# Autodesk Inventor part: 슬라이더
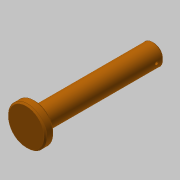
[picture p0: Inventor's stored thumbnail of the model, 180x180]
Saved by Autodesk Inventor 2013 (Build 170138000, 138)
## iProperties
Created: 2019-01
Part Number: 슬라이더
Material: 강철, 연강
Document SubType Name: Modeling
Designer: mduedu
Density: 1 g/cm^3
Author: mduedu
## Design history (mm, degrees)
sketch "스케치1"
  geometry: L1 (0, 0)-(6, 0); L2 (6, 0)-(6, 13); L3 (6, 13)-(0, 13); L4 (0, 13)-(0, 0); L5 (6, 0)-(86, 0); L6 (86, 0)-(86, 7); L7 (86, 7)-(6, 7); L8 (6, 7)-(6, 0)
  constraints: 16 end point, 4 parallel, 2 horizontal, 2 perpendicular
  dimensions: "d0" = 86 distance between parallel lines of L6 L4; "d2" = 6 distance of L2.end L3.end; "d3" = 26 diameter of L3 L1; "d4" = 14 diameter of L7 L5
revolve "회전1" sketch "스케치1" stored, may be unused: angle "d5" = 90 deg
chamfer "모따기1" distance "d6" = 1; stored, may be unused: second distance "d7" = 2, angle "d8" = 45 deg
chamfer "모따기4" distance "d24" = 1; stored, may be unused: second distance "d25" = 2, angle "d28" = 30 deg
sketch "스케치3"
  geometry: L1 (86, 6)-(86, -6) reference; C1 r 1 at (81, 0); 1 further point
  constraints: 1 centre point, 1 horizontal alignment
  dimensions: "d34" = 2 diameter of C1; "d36" = 5 distance from line of C1.centre L1
extrude "돌출1" cut sketch "스케치3" stored distance "d37" = 10; taper "d38" = 0 deg
node "솔리드1"
